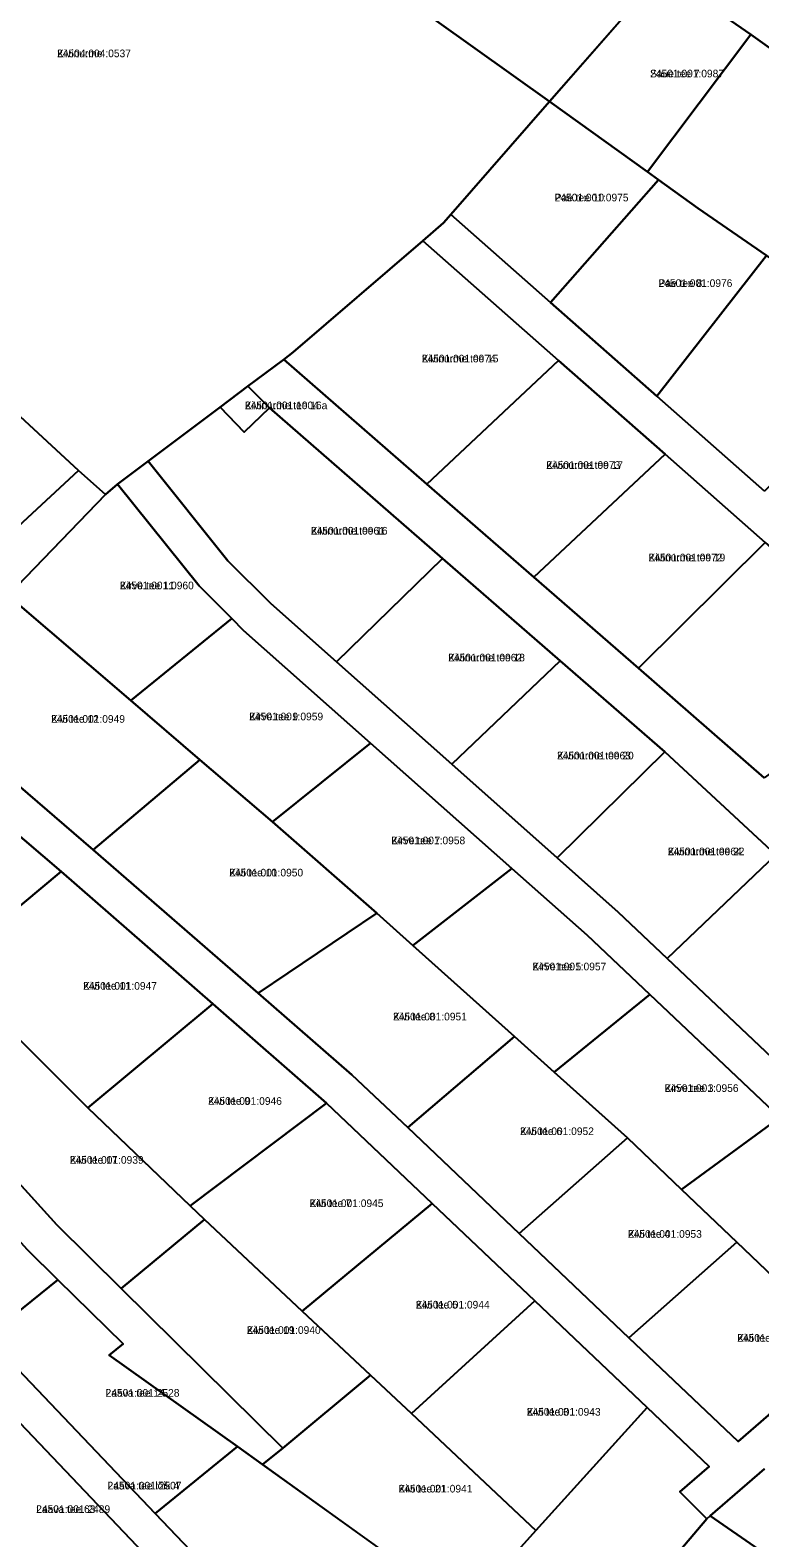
# Model space of a CAD drawing. Extents: x 551291 to 575799, y 6581704 to 6610137.
# Drawn here: x 559383.3 to 559526.5, y 6593475.6 to 6593771.7 of the extents above; entities that cross this region are included whole.
import ezdxf

# ---------------------------------------------------------------- set-up
doc = ezdxf.new("R2010")
doc.units = 0
for name, color, linetype in [('L_AADRESS', 7, 'Continuous'), ('PIIR', 7, 'Continuous'), ('TUNNUS', 7, 'Continuous')]:
    doc.layers.add(name, color=color, linetype=linetype)

msp = doc.modelspace()

# ---------------------------------------------------------------- linework, layer by layer
at = {"layer": 'PIIR'}
for points in [[(559358.56, 6593852.25), (559389.79, 6593868.69), (559395.77, 6593868.26), (559508.79, 6593784.67), (559485.21, 6593757.68), (559366.12, 6593842.62)], [(559400.41, 6593682.53), (559398.02, 6593680.52), (559392.78, 6593685.23), (559372.46, 6593703.92), (559362.29, 6593713.22), (559353.5, 6593721.24), (559344.69, 6593729.33), (559331.38, 6593741.49), (559309.88, 6593761.17), (559271.2, 6593795.97), (559293.37, 6593811.67), (559299.35, 6593813.89), (559312.56, 6593828.02), (559358.56, 6593852.25), (559366.12, 6593842.62), (559485.21, 6593757.68), (559465.82, 6593735.48), (559464.42, 6593733.88), (559460.32, 6593730.35), (559434.91, 6593708.44), (559433.03, 6593707.03), (559426.01, 6593701.76), (559420.53, 6593697.64), (559406.41, 6593687.04)], [(559504.42, 6593743.87), (559485.21, 6593757.68), (559507.27, 6593782.93), (559524.69, 6593770.84)], [(559506.6, 6593742.3), (559504.42, 6593743.87), (559524.69, 6593770.84), (559550.37, 6593752.51), (559532.78, 6593729.83), (559530.4, 6593725.69), (559527.81, 6593727.46), (559514.3, 6593736.72)], [(559223.23, 6593761.3), (559228.92, 6593765.5), (559235.7, 6593757.89), (559238.81, 6593754.43), (559242.5, 6593750.32), (559254.62, 6593736.88), (559270.18, 6593722.86), (559275.86, 6593717.83), (559294.69, 6593700.86), (559328.18, 6593670.83), (559352.99, 6593648.57), (559371.73, 6593665.8), (559392.78, 6593685.23), (559398.02, 6593680.52), (559378.93, 6593660.64), (559360.43, 6593641.06), (559356.05, 6593636.44), (559342.59, 6593648.47), (559333.26, 6593656.84), (559313.57, 6593674.54), (559290.82, 6593694.98), (559259.32, 6593723.24), (559249.66, 6593731.86)], [(559485.37, 6593718.23), (559465.82, 6593735.48), (559485.21, 6593757.68), (559504.42, 6593743.87), (559506.6, 6593742.3)], [(559506.26, 6593699.8), (559485.37, 6593718.23), (559506.6, 6593742.3), (559514.3, 6593736.72), (559527.81, 6593727.46)], [(559461.13, 6593682.55), (559433.03, 6593707.03), (559434.91, 6593708.44), (559460.32, 6593730.35), (559486.97, 6593706.84)], [(559527.41, 6593681.15), (559506.26, 6593699.8), (559527.81, 6593727.46), (559530.4, 6593725.69), (559554.82, 6593708.55)], [(559341.04, 6593694.76), (559362.29, 6593713.22), (559372.46, 6593703.92), (559392.78, 6593685.23), (559371.73, 6593665.8), (559350.14, 6593686.7)], [(559482.14, 6593664.25), (559461.13, 6593682.55), (559486.97, 6593706.84), (559507.87, 6593688.4)], [(559425.25, 6593692.75), (559420.53, 6593697.64), (559426.01, 6593701.76), (559430.23, 6593697.54)], [(559422.04, 6593667.5), (559406.41, 6593687.04), (559420.53, 6593697.64), (559425.25, 6593692.75), (559430.23, 6593697.54), (559464.22, 6593667.92), (559443.37, 6593647.64), (559430.49, 6593659.07)], [(559502.67, 6593646.37), (559482.14, 6593664.25), (559507.87, 6593688.4), (559527.51, 6593671.08)], [(559403, 6593640.02), (559378.93, 6593660.64), (559398.02, 6593680.52), (559400.41, 6593682.53), (559416.41, 6593662.54), (559422.83, 6593656.13)], [(559527.34, 6593624.88), (559502.67, 6593646.37), (559527.51, 6593671.08), (559556.33, 6593645.65)], [(559466, 6593627.54), (559443.37, 6593647.64), (559464.22, 6593667.92), (559487.29, 6593647.83)], [(559395.61, 6593610.72), (559360.43, 6593641.06), (559378.93, 6593660.64), (559403, 6593640.02), (559416.54, 6593628.43)], [(559416.54, 6593628.43), (559403, 6593640.02), (559422.83, 6593656.13), (559425.16, 6593653.79), (559450.07, 6593631.68), (559430.85, 6593616.2)], [(559486.72, 6593609.15), (559466, 6593627.54), (559487.29, 6593647.83), (559507.82, 6593629.95)], [(559366.93, 6593587.72), (559342.95, 6593611.69), (559360.96, 6593630.7), (559389.32, 6593606.49)], [(559451.3, 6593598.28), (559430.85, 6593616.2), (559450.07, 6593631.68), (559477.82, 6593607.05), (559458.35, 6593591.96)], [(559498.67, 6593598.51), (559486.72, 6593609.15), (559507.82, 6593629.95), (559529.63, 6593609.71), (559508.31, 6593589.38)], [(559428.01, 6593582.57), (559395.61, 6593610.72), (559416.54, 6593628.43), (559430.85, 6593616.2), (559451.3, 6593598.28)], [(559528.87, 6593569.93), (559508.31, 6593589.38), (559529.63, 6593609.71), (559550.44, 6593590.38)], [(559378.92, 6593575.72), (559366.93, 6593587.72), (559389.32, 6593606.49), (559419.11, 6593580.47), (559394.61, 6593560.03)], [(559478.34, 6593574.06), (559458.35, 6593591.96), (559477.82, 6593607.05), (559492.58, 6593593.95), (559504.89, 6593582.3), (559486.14, 6593567.07)], [(559446.43, 6593566.57), (559428.01, 6593582.57), (559451.3, 6593598.28), (559458.35, 6593591.96), (559478.34, 6593574.06), (559457.36, 6593556.17)], [(559500.51, 6593554.18), (559486.14, 6593567.07), (559504.89, 6593582.3), (559530.39, 6593558.18), (559511.11, 6593544.05)], [(559414.67, 6593540.83), (559394.61, 6593560.03), (559419.11, 6593580.47), (559441.42, 6593560.98)], [(559388.48, 6593537.08), (559364.59, 6593563.37), (559378.92, 6593575.72), (559394.61, 6593560.03), (559414.67, 6593540.83), (559417.49, 6593538.13), (559401.12, 6593524.59)], [(559479.26, 6593535.36), (559457.36, 6593556.17), (559478.34, 6593574.06), (559486.14, 6593567.07), (559500.51, 6593554.18)], [(559417.49, 6593538.13), (559414.67, 6593540.83), (559441.42, 6593560.98), (559462.14, 6593541.29), (559436.64, 6593520.16)], [(559521.99, 6593533.67), (559511.11, 6593544.05), (559530.39, 6593558.18), (559561.59, 6593528.66), (559543.57, 6593513.06)], [(559500.8, 6593514.9), (559479.26, 6593535.36), (559500.51, 6593554.18), (559511.11, 6593544.05), (559521.99, 6593533.67)], [(559450.08, 6593507.53), (559436.64, 6593520.16), (559462.14, 6593541.29), (559482.29, 6593522.15), (559458.08, 6593500.02)], [(559432.87, 6593493.22), (559401.12, 6593524.59), (559417.49, 6593538.13), (559436.64, 6593520.16), (559450.08, 6593507.53)], [(559363.74, 6593521.61), (559380.27, 6593534.92), (559382.69, 6593532.27), (559388.67, 6593526.29), (559373.66, 6593514.2), (559380.83, 6593508.71), (559407.81, 6593480.38), (559435.5, 6593451.37), (559438.64, 6593448.01), (559429.05, 6593446.56), (559428.92, 6593448.05), (559407.99, 6593470.04), (559376.11, 6593503.53), (559358.28, 6593517.14)], [(559522.2, 6593494.56), (559500.8, 6593514.9), (559521.99, 6593533.67), (559543.57, 6593513.06)], [(559373.66, 6593514.2), (559388.67, 6593526.29), (559401.49, 6593513.72), (559398.77, 6593511.46), (559423.97, 6593493.54), (559407.81, 6593480.38), (559380.83, 6593508.71)], [(559482.51, 6593477.08), (559458.08, 6593500.02), (559482.29, 6593522.15), (559504.36, 6593501.18)], [(559468.58, 6593461.51), (559428.88, 6593490.04), (559432.87, 6593493.22), (559450.08, 6593507.53), (559458.08, 6593500.02), (559482.51, 6593477.08)], [(559360.94, 6593491.68), (559376.11, 6593503.53), (559407.99, 6593470.04), (559391.57, 6593458.83), (559377.61, 6593473.41)], [(559488.67, 6593447.02), (559468.58, 6593461.51), (559482.51, 6593477.08), (559504.36, 6593501.18), (559516.51, 6593489.63), (559510.75, 6593484.65), (559516.09, 6593479.32)], [(559407.81, 6593480.38), (559423.97, 6593493.54), (559428.88, 6593490.04), (559458.47, 6593468.77), (559435.5, 6593451.37)], [(559516.09, 6593479.32), (559516.73, 6593479.92), (559534.96, 6593467.27), (559509.57, 6593432.53), (559488.67, 6593447.02)]]:
    msp.add_lwpolyline(points, close=True, dxfattribs=at)
for points in [[(559550.37, 6593752.51), (559524.69, 6593770.84), (559507.27, 6593782.93), (559508.79, 6593784.67), (559512.57, 6593788.38), (559534.19, 6593773.28)], [(559527.51, 6593671.08), (559507.87, 6593688.4), (559486.97, 6593706.84), (559460.32, 6593730.35), (559464.42, 6593733.88), (559465.82, 6593735.48), (559485.37, 6593718.23), (559506.26, 6593699.8), (559527.41, 6593681.15)], [(559529.63, 6593609.71), (559507.82, 6593629.95), (559487.29, 6593647.83), (559464.22, 6593667.92), (559430.23, 6593697.54), (559426.01, 6593701.76), (559433.03, 6593707.03), (559461.13, 6593682.55), (559482.14, 6593664.25), (559502.67, 6593646.37), (559527.34, 6593624.88)], [(559530.39, 6593558.18), (559504.89, 6593582.3), (559492.58, 6593593.95), (559477.82, 6593607.05), (559450.07, 6593631.68), (559425.16, 6593653.79), (559422.83, 6593656.13), (559416.41, 6593662.54), (559400.41, 6593682.53), (559406.41, 6593687.04), (559422.04, 6593667.5), (559430.49, 6593659.07), (559443.37, 6593647.64), (559466, 6593627.54), (559486.72, 6593609.15), (559498.67, 6593598.51), (559508.31, 6593589.38), (559528.87, 6593569.93)], [(559360.43, 6593641.06), (559395.61, 6593610.72), (559428.01, 6593582.57), (559446.43, 6593566.57), (559457.36, 6593556.17), (559479.26, 6593535.36), (559500.8, 6593514.9), (559522.2, 6593494.56), (559543.57, 6593513.06)], [(559527.37, 6593489.15), (559516.73, 6593479.92), (559516.09, 6593479.32), (559510.75, 6593484.65), (559516.51, 6593489.63), (559504.36, 6593501.18), (559482.29, 6593522.15), (559462.14, 6593541.29), (559441.42, 6593560.98), (559419.11, 6593580.47), (559389.32, 6593606.49), (559360.96, 6593630.7)], [(559364.59, 6593563.37), (559388.48, 6593537.08), (559401.12, 6593524.59), (559432.87, 6593493.22), (559428.88, 6593490.04), (559423.97, 6593493.54), (559398.77, 6593511.46), (559401.49, 6593513.72), (559388.67, 6593526.29), (559382.69, 6593532.27)], [(559534.96, 6593467.27), (559516.73, 6593479.92), (559527.37, 6593489.15)]]:
    msp.add_lwpolyline(points, dxfattribs=at)

# ---------------------------------------------------------------- texts
at = {"layer": 'L_AADRESS'}
for s, p in [('Kivinurme', (559388.54, 6593766.38)), ('Saue tee 7', (559504.95, 6593762.42)), ('Pae tee 10', (559486.21, 6593738.07)), ('Pae tee 8', (559506.59, 6593721.26)), ('Kivinurme tee 15', (559460.13, 6593706.45)), ('Kivinurme tee 16a', (559425.42, 6593697.26)), ('Kivinurme tee 17', (559484.57, 6593685.54)), ('Kivinurme tee 16', (559438.37, 6593672.64)), ('Kivinurme tee 19', (559504.64, 6593667.38)), ('Kirve tee 11', (559400.88, 6593661.89)), ('Kivinurme tee 18', (559465.32, 6593647.73)), ('Kivi tee 12', (559387.37, 6593635.68)), ('Kirve tee 9', (559426.26, 6593636.16)), ('Kivinurme tee 20', (559486.67, 6593628.49)), ('Kirve tee 7', (559454.15, 6593611.82)), ('Kivinurme tee 22', (559508.41, 6593609.66)), ('Kivi tee 10', (559422.34, 6593605.5)), ('Kirve tee 5', (559481.84, 6593587.06)), ('Kivi tee 11', (559393.65, 6593583.26)), ('Kivi tee 8', (559454.48, 6593577.23)), ('Kirve tee 3', (559507.8, 6593563.18)), ('Kivi tee 9', (559418.17, 6593560.65)), ('Kivi tee 6', (559479.41, 6593554.71)), ('Kivi tee 17', (559391.04, 6593549.08)), ('Kivi tee 7', (559438.11, 6593540.57)), ('Kivi tee 4', (559500.6, 6593534.54)), ('Kivi tee 5', (559458.95, 6593520.65)), ('Kivi tee 19', (559425.78, 6593515.67)), ('Kivi tee 2', (559522.05, 6593514.12)), ('Laava tee 14', (559398.07, 6593503.33)), ('Kivi tee 3', (559480.73, 6593499.61)), ('Laava tee lõik 4', (559398.46, 6593485.12)), ('Kivi tee 21', (559455.57, 6593484.52)), ('Laava tee 63', (559384.46, 6593480.5))]:
    msp.add_text(s, height=1.5, dxfattribs=at).set_placement(p)
at = {"layer": 'TUNNUS'}
for s, p in [('24504:004:0537', (559388.54, 6593766.38)), ('24501:001:0987', (559504.95, 6593762.42)), ('24501:001:0975', (559486.21, 6593738.07)), ('24501:001:0976', (559506.59, 6593721.26)), ('24501:001:0974', (559460.13, 6593706.45)), ('24501:001:1004', (559425.42, 6593697.26)), ('24501:001:0973', (559484.57, 6593685.54)), ('24501:001:0961', (559438.37, 6593672.64)), ('24501:001:0972', (559504.64, 6593667.38)), ('24501:001:0960', (559400.88, 6593661.89)), ('24501:001:0962', (559465.32, 6593647.73)), ('24501:001:0949', (559387.37, 6593635.68)), ('24501:001:0959', (559426.26, 6593636.16)), ('24501:001:0963', (559486.67, 6593628.49)), ('24501:001:0958', (559454.15, 6593611.82)), ('24501:001:0964', (559508.41, 6593609.66)), ('24501:001:0950', (559422.34, 6593605.5)), ('24501:001:0957', (559481.84, 6593587.06)), ('24501:001:0947', (559393.65, 6593583.26)), ('24501:001:0951', (559454.48, 6593577.23)), ('24501:001:0956', (559507.8, 6593563.18)), ('24501:001:0946', (559418.17, 6593560.65)), ('24501:001:0952', (559479.41, 6593554.71)), ('24501:001:0939', (559391.04, 6593549.08)), ('24501:001:0945', (559438.11, 6593540.57)), ('24501:001:0953', (559500.6, 6593534.54)), ('24501:001:0944', (559458.95, 6593520.65)), ('24501:001:0940', (559425.78, 6593515.67)), ('24501:001:0954', (559522.05, 6593514.12)), ('24501:001:2528', (559398.07, 6593503.33)), ('24501:001:0943', (559480.73, 6593499.61)), ('24501:001:2507', (559398.46, 6593485.12)), ('24501:001:0941', (559455.57, 6593484.52)), ('24501:001:2489', (559384.46, 6593480.5))]:
    msp.add_text(s, height=1.5, dxfattribs=at).set_placement(p)

doc.saveas('drawing.dxf')
